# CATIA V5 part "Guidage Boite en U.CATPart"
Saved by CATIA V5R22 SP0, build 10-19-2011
Part number: Guidage boite en U
Bounding box of the stored display mesh (mm): x -109 to 109, y 0 to 162.406, z 0 to 16.6
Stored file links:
  D:\PER\CAO_PER_MODIF_2025\CAO_PER_pick&place_2024P\Sous_Ensemble_Boite\Guidage Boite en U.CATPart
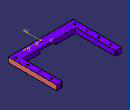
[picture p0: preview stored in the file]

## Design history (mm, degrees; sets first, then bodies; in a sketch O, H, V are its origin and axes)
Body1 (main body)
  Sketch1 on xy-plane, origin (0, 0, 0), H (1, 0, 0), V (0, 1, 0)
    point P1 (-109, 0)
    line L1 (-109, 0) -> (0, 0)
    point P2 (0, 0)
    point P3 (0, 27.406)
    line L2 (0, 27.406) -> (-89, 27.406)
    line L3 (-89, 27.406) -> (-89, 162.406)
    line L4 (-89, 162.406) -> (-109, 162.406)
    line L5 (-109, 162.406) -> (-109, 0)
    line L6 (0, 27.406) -> (0, 0)
    distance L2 L1 = 27.406
    distance L6 L3 = 89
    distance L5 L3 = 20
    distance L2 L4 = 135
    coincidence: P1 H, P2 V, P3 V, O P2
    horizontal: L1 H, L2 H, L4 H
    vertical: L3 V, L5 V, L6 V
  Pad1: profile Sketch1, direction (0, 0, 1), length 16.6
  Sketch2 on start face of Pad1, origin (0, 0, 0), H (1, 0, 0), V (0, -1, 0)
    circle A1 centre (-99, -15) radius 3.25
    point P1 (-99, -15)
    circle A2 centre (-99, -55) radius 3.25
    point P2 (-99, -55)
    circle A3 centre (-99, -95) radius 3.25
    point P3 (-99, -95)
    construction line L1 (-99, -55) -> (-99, -15)
    axis line L2 (-99, -95) -> (-99, -55)
    reference projected line E1 (-109, 0) -> (0, 0) from edge [start face of Pad1 | face of Pad1 from Sketch1.L1]
    reference projected line E2 (-109, -162.406) -> (-109, 0) from edge [start face of Pad1 | face of Pad1 from Sketch1.L5]
    radius A1 = 3.25
    radius A2 = 3.25
    radius A3 = 3.25
    distance P1 E1 = 15
    distance P1 E2 = 10
    distance P2 P3 = 40
    distance P1 P2 = 40
    vertical: L2 V, L1 V
  Pocket1: profile Sketch2, direction (0, 0, 1), through (limit type 3)
  Sketch3 on start face of Pad1, origin (0, 0, 0), H (1, 0, 0), V (0, -1, 0)
    point P1 (-99, -15)
    point P2 (-94, -12.1132)
    point P3 (-99, -9.2265)
    point P4 (-104, -12.1132)
    point P5 (-104, -17.8868)
    point P6 (-99, -20.7735)
    point P7 (-94, -17.8868)
    point P8 (-96.5, -10.6699)
    line L1 (-94, -12.1132) -> (-99, -9.2265)
    line L2 (-99, -9.2265) -> (-104, -12.1132)
    line L3 (-104, -12.1132) -> (-104, -17.8868)
    line L4 (-104, -17.8868) -> (-99, -20.7735)
    line L5 (-99, -20.7735) -> (-94, -17.8868)
    line L6 (-94, -17.8868) -> (-94, -12.1132)
    construction line L7 (-99, -15) -> (-96.5, -10.6699)
    construction circle A1 centre (-99, -15) radius 5.7735
    construction arc A2 centre (-99, -20.7735) radius 5.7735 from (-104, -17.8868) to (-94, -17.8868) cw
    construction arc A3 centre (-99, -9.2265) radius 5.7735 from (-104, -12.1132) to (-94, -12.1132) ccw
    point P9 (-99, -55)
    point P10 (-94, -52.1132)
    point P11 (-99, -49.2265)
    point P12 (-104, -52.1132)
    point P13 (-104, -57.8868)
    point P14 (-99, -60.7735)
    point P15 (-94, -57.8868)
    point P16 (-96.5, -50.6699)
    line L8 (-94, -52.1132) -> (-99, -49.2265)
    line L9 (-99, -49.2265) -> (-104, -52.1132)
    line L10 (-104, -52.1132) -> (-104, -57.8868)
    line L11 (-104, -57.8868) -> (-99, -60.7735)
    line L12 (-99, -60.7735) -> (-94, -57.8868)
    line L13 (-94, -57.8868) -> (-94, -52.1132)
    construction line L14 (-99, -55) -> (-96.5, -50.6699)
    construction circle A4 centre (-99, -55) radius 5.7735
    construction arc A5 centre (-99, -60.7735) radius 5.7735 from (-104, -57.8868) to (-94, -57.8868) cw
    construction arc A6 centre (-99, -49.2265) radius 5.7735 from (-104, -52.1132) to (-94, -52.1132) ccw
    point P17 (-99, -95)
    point P18 (-94, -92.1132)
    point P19 (-99, -89.2265)
    point P20 (-104, -92.1132)
    point P21 (-104, -97.8868)
    point P22 (-99, -100.7735)
    point P23 (-94, -97.8868)
    point P24 (-96.5, -90.6699)
    line L15 (-94, -92.1132) -> (-99, -89.2265)
    line L16 (-99, -89.2265) -> (-104, -92.1132)
    line L17 (-104, -92.1132) -> (-104, -97.8868)
    line L18 (-104, -97.8868) -> (-99, -100.7735)
    line L19 (-99, -100.7735) -> (-94, -97.8868)
    line L20 (-94, -97.8868) -> (-94, -92.1132)
    construction circle A7 centre (-99, -95) radius 5.7735
    construction arc A8 centre (-99, -100.7735) radius 5.7735 from (-104, -97.8868) to (-94, -97.8868) cw
    construction arc A9 centre (-99, -89.2265) radius 5.7735 from (-104, -92.1132) to (-94, -92.1132) ccw
    reference projected circle E1 centre (-99, -95) radius 3.25 from edge [start face of Pad1 | face of Pocket1 from Sketch2.A3]
    reference projected circle E2 centre (-99, -55) radius 3.25 from edge [start face of Pad1 | face of Pocket1 from Sketch2.A2]
    reference projected circle E3 centre (-99, -15) radius 3.25 from edge [start face of Pad1 | face of Pocket1 from Sketch2.A1]
    axis line L21 (-132.2845, -115) -> (-27.6372, -115)
    point P27 (-94, -132.1132)
    point P28 (-99, -129.2265)
    line L22 (-99, -129.2265) -> (-94, -132.1132)
    point P29 (-104, -132.1132)
    line L23 (-104, -132.1132) -> (-99, -129.2265)
    point P30 (-104, -137.8868)
    line L24 (-104, -137.8868) -> (-104, -132.1132)
    point P31 (-99, -140.7735)
    line L25 (-99, -140.7735) -> (-104, -137.8868)
    point P32 (-94, -137.8868)
    line L26 (-94, -137.8868) -> (-99, -140.7735)
    line L27 (-94, -132.1132) -> (-94, -137.8868)
    projected circle E4 centre (-99, -95) radius 3.25 from edge [start face of Pad1 | face of Pocket1 from Sketch2.A3]
    circle A10 centre (-99, -135) radius 3.25
    distance L17 L20 = 10
    distance L21 P17 = 20
    coincidence: A1 P2, A1 P3, A1 P4, A1 P5, A1 P6, A1 P7, A2 P1, A3 P1, A4 P10, A4 P11, A4 P12, A4 P13, A4 P14, A4 P15, A5 P9, A6 P9, A7 P18, A7 P19, A7 P20, A7 P21, A7 P22, A7 P23, A8 P17, A9 P17, P7 L13, P15 L20
    midpoint: P8 L1, P16 L8, P24 L15
    parallelism: L1 L4, L8 L11, L15 L18, L6 L13, L13 L20
    concentricity: P17 E1, P9 E2, P1 E3
    vertical: L20 V
    horizontal: L21 H
    symmetry: P23 P27 L21, P22 P28 L21, L19 L22 L21, P21 P29 L21, L18 L23 L21, P20 P30 L21, L17 L24 L21, P19 P31 L21, L16 L25 L21, P18 P32 L21, L15 L26 L21, L20 L27 L21, E4 A10 L21
  Pocket2: profile Sketch3, direction (0, 0, 1), length 6
  Chamfer1: length 1, angle 45, on edge [start face of Pad1 | face of Pocket2 from Sketch3.L6]; edge [start face of Pad1 | face of Pocket2 from Sketch3.L1]; edge [start face of Pad1 | face of Pocket2 from Sketch3.L2]; edge [start face of Pad1 | face of Pocket2 from Sketch3.L3]; edge [start face of Pad1 | face of Pocket2 from Sketch3.L4]; edge [start face of Pad1 | face of Pocket2 from Sketch3.L5]; edge [start face of Pad1 | face of Pocket2 from Sketch3.L8]; edge [start face of Pad1 | face of Pocket2 from Sketch3.L13]; edge [start face of Pad1 | face of Pocket2 from Sketch3.L12]; edge [start face of Pad1 | face of Pocket2 from Sketch3.L11]; edge [start face of Pad1 | face of Pocket2 from Sketch3.L10]; edge [start face of Pad1 | face of Pocket2 from Sketch3.L9]; edge [start face of Pad1 | face of Pocket2 from Sketch3.L16]; edge [start face of Pad1 | face of Pocket2 from Sketch3.L15]; edge [start face of Pad1 | face of Pocket2 from Sketch3.L20]; edge [start face of Pad1 | face of Pocket2 from Sketch3.L19]; edge [start face of Pad1 | face of Pocket2 from Sketch3.L18]; edge [start face of Pad1 | face of Pocket2 from Sketch3.L17]; edge [start face of Pad1 | face of Pocket2 from Sketch3.L26]; edge [start face of Pad1 | face of Pocket2 from Sketch3.L22]; edge [start face of Pad1 | face of Pocket2 from Sketch3.L23]; edge [start face of Pad1 | face of Pocket2 from Sketch3.L24]; edge [start face of Pad1 | face of Pocket2 from Sketch3.L25]; edge [start face of Pad1 | face of Pocket2 from Sketch3.L27]
  Chamfer2: length 5, angle 30, on edge [face of Pad1 from Sketch1.L4 | face of Pad1 from Sketch1.L3]
  Mirror1: of the body so far, about face of Pad1 from Sketch1.L6
  Sketch4 on face of Pad1, origin (0, 0, 0), H (1, 0, 0), V (0, -1, 0)
    line L1 (-30, -20) -> (-23, -20)
    line L2 (30, 0) -> (-30, 0)
    line L3 (-30, 0) -> (-30, -20)
    line L4 (-23, -20) -> (-23, -30)
    line L5 (-23, -30) -> (30, -30)
    line L6 (30, -30) -> (30, 0)
    reference projected line E1 (0, 0) -> (-109, 0) from edge [face of Pad1 | face of Pad1]
    axis line L7 (0, 18.626) -> (0, -51.4584)
    distance L4 L3 = 7
    distance L2 L5 = 30
    distance L2 L1 = 20
    distance L6 L3 = 60
    horizontal: L1 H, L2 H, L5 H
    vertical: L3 V, L4 V, L6 V, L7 V
    coincidence: L2 E1, L7 V
    symmetry: L6 L3 L7
  Pocket3: profile Sketch4, direction (0, 0, 1), length 10
  Sketch5 on end face of Pocket3, origin (0, 0, 10), H (1, 0, 0), V (0, -1, 0)
    point P1 (-17.2, -17.2)
    point P2 (15.2, -2.8)
    reference projected line E1 (30, -27.406) -> (30, 0) from edge [face of Pad1 | face of Pocket3 from Sketch4.L6]
    reference projected line E2 (-30, 0) -> (-30, -20) from edge [face of Pad1 | face of Pocket3 from Sketch4.L3]
    point P3 (15.2, -2.8)
    point P4 (-17.2, -17.2)
    reference projected line E3 (-30, -20) -> (-23, -20) from edge [face of Pad1 | face of Pocket3 from Sketch4.L1]
    reference projected line E4 (30, 0) -> (-30, 0) from edge [face of Pad1 | end face of Pocket3]
    distance P2 E1 = 14.8
    distance P1 E2 = 12.8
    distance P4 E3 = 2.8
    distance E4 P3 = 2.8
    coincidence: P3 P2, P4 P1
  DatumCurve1
  Sketch6 on end face of Pocket3, origin (-13.45, 2.8, 10), H (1, 0, 0), V (0, -1, 0)
    point P1 (0, -18.4308)
    reference projected arc E1 centre (0, -18.4308) radius 1.55 from (1.55, -18.4308) to (-1.55, -18.4308) ccw from edge of DatumCurve1
    concentricity: P1 E1
  Hole1: placed by Sketch6, at (-13.45, 21.2308, 10) direction (0, 0, 1), diameter 2.459, through (limit type 3), threaded "M3", thread diameter 3, thread depth 6.6, pitch 0.5
  DatumCurve2
  Sketch7 on end face of Pocket3, origin (8.95, 17.2, 10), H (1, 0, 0), V (0, -1, 0)
    point P1 (-0.2, 6.2692)
    reference projected arc E1 centre (-0.2, 6.2692) radius 1.55 from (-1.75, 6.2692) to (1.35, 6.2692) ccw from edge of DatumCurve2
    concentricity: P1 E1
  Hole2: placed by Sketch7, at (8.75, 10.9308, 10) direction (0, 0, 1), diameter 2.459, through (limit type 3), threaded "M3", thread diameter 3, thread depth 6.6, pitch 0.5
  RectPattern1: of Pocket1, direction 1 instances 2, spacing 40, along edge [face of Pad1 | face of Pad1 from Sketch1.L3]
  RectPattern2: of Pocket2, direction 1 instances 2, spacing 40, along edge [face of Pad1 | face of Pad1 from Sketch1.L3]
  Plane1: type Offset, Offset 88.25, RefPlane face of Pad1 from Sketch1.L3, reversed
  Sketch8 on face of Pad1, origin (0, 0, 0), H (1, 0, 0), V (0, -1, 0)
    circle A1 centre (99, -135) radius 3.25
    point P1 (99, -135)
    reference projected circle E1 centre (99, -95) radius 3.25 from edge [face of Mirror1 | face of Mirror1]
    reference projected line E2 (109, -162.406) -> (109, 0) from edge [face of Mirror1 | face of Pad1]
    reference projected line E3 (89, -27.406) -> (89, -159.5192) from edge [face of Mirror1 | face of Mirror1]
    radius A1 = 3.25
    distance E1 A1 = 40
    equidistance: E2 E3 P1
  Pocket4: profile Sketch8, direction (0, 0, 1), length 26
